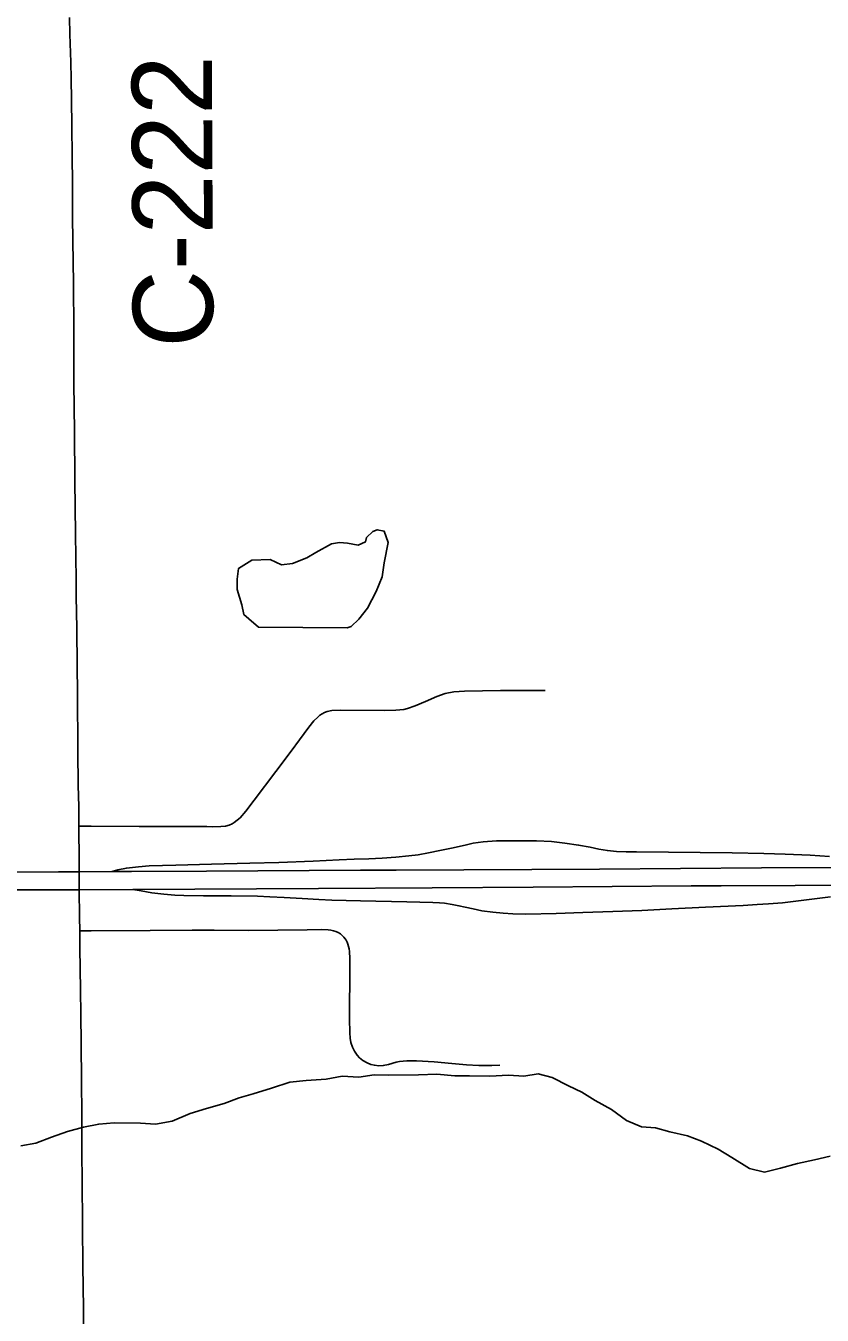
# Model space of a CAD drawing. Extents: x 0 to 34, y 0 to 22.
# Drawn here: x 19.216 to 19.78, y 18.221 to 19.134 of the extents above; entities that cross this region are included whole.
import ezdxf

# ---------------------------------------------------------------- set-up
doc = ezdxf.new("R2010")
doc.units = 0
for name, color, linetype in [('GM_X_County_Road', 7, 'Continuous'), ('GM_X_County_Road_Text', 7, 'Continuous'), ('GM_X_Interchange_Ramps', 7, 'Continuous'), ('GM_X_Interstate_Route', 7, 'Continuous'), ('GM_X_Minor_Lake', 7, 'Continuous'), ('GM_X_Minor_River', 7, 'Continuous'), ('GM_X_Township_Road', 7, 'Continuous')]:
    doc.layers.add(name, color=color, linetype=linetype)

msp = doc.modelspace()

# ---------------------------------------------------------------- linework, layer by layer
at = {"layer": 'GM_X_County_Road'}
for points in [[(19.25311, 18.56694), (19.25303, 18.58087), (19.25268, 18.59578), (19.25246, 18.62003), (19.25212, 18.66166), (19.25198, 18.68029), (19.25169, 18.70694), (19.25129, 18.72987), (19.25119, 18.74165), (19.25083, 18.77391), (19.25026, 18.81171), (19.25004, 18.84653), (19.24967, 18.88072), (19.24957, 18.90185), (19.24955, 18.91801), (19.24925, 18.95156), (19.24888, 18.9814), (19.24862, 18.9988), (19.24866, 19.02231), (19.24835, 19.04152), (19.24813, 19.06263), (19.24796, 19.08123), (19.24766, 19.09613), (19.24734, 19.10792), (19.24665, 19.1278), (19.24644, 19.13962)], [(19.25372, 18.49286), (19.25357, 18.50256), (19.25338, 18.52187), (19.25329, 18.53477), (19.25325, 18.54173), (19.25311, 18.56694)], [(19.257, 18.16696), (19.25674, 18.19016), (19.2563, 18.22556), (19.25602, 18.25597), (19.25569, 18.28392), (19.25549, 18.31685), (19.25531, 18.33487), (19.25521, 18.36284), (19.25499, 18.38645), (19.25467, 18.41317), (19.25441, 18.43367), (19.25425, 18.45105), (19.25391, 18.48083), (19.25372, 18.49286)]]:
    msp.add_lwpolyline(points, dxfattribs=at)
at = {"layer": 'GM_X_Interchange_Ramps'}
for points in [[(19.27664, 18.53491), (19.28082, 18.53605), (19.28679, 18.53735), (19.29537, 18.53828), (19.30301, 18.53886), (19.3217, 18.53936), (19.34715, 18.54004), (19.3743, 18.54077), (19.39487, 18.54129), (19.4192, 18.54235), (19.43746, 18.54314), (19.44801, 18.54357), (19.45856, 18.54401), (19.46787, 18.5444), (19.47755, 18.54502), (19.48679, 18.54599), (19.4935, 18.54683), (19.50078, 18.54822), (19.50876, 18.54976), (19.51715, 18.55157), (19.52681, 18.55367), (19.5324, 18.55493), (19.53954, 18.5559), (19.54905, 18.55659), (19.56304, 18.55658), (19.57731, 18.55672), (19.58793, 18.55621), (19.59732, 18.55503), (19.60712, 18.55363), (19.61537, 18.55209), (19.62152, 18.55082), (19.62754, 18.5497), (19.63383, 18.54913), (19.64083, 18.54885), (19.64822, 18.54877), (19.71595, 18.54826), (19.73831, 18.54777), (19.75332, 18.54725), (19.77119, 18.54639), (19.78481, 18.54563)], [(19.29138, 18.5221), (19.29721, 18.52114), (19.30479, 18.51989), (19.31321, 18.51885), (19.32111, 18.51825), (19.32744, 18.51801), (19.34137, 18.51776), (19.36089, 18.51779), (19.37959, 18.51736), (19.38831, 18.51703), (19.3986, 18.51651), (19.41138, 18.51585), (19.42321, 18.51511), (19.4322, 18.51465), (19.4527, 18.51408), (19.48544, 18.51356), (19.50393, 18.51303), (19.5085, 18.51272), (19.51204, 18.51241), (19.51744, 18.51157), (19.52232, 18.51074), (19.52678, 18.5097), (19.53249, 18.50845), (19.53863, 18.5072), (19.54631, 18.50615), (19.55371, 18.50534), (19.56044, 18.505), (19.56968, 18.50479), (19.59118, 18.50527), (19.6101, 18.50583), (19.63133, 18.50663), (19.65196, 18.50743), (19.67314, 18.50847), (19.69694, 18.50964), (19.72373, 18.51095), (19.73351, 18.51146), (19.74172, 18.51198), (19.75158, 18.5128), (19.7856, 18.51689)]]:
    msp.add_lwpolyline(points, dxfattribs=at)
at = {"layer": 'GM_X_Interstate_Route'}
for points in [[(18.06769, 18.52783), (18.1722, 18.52848), (18.31435, 18.52952), (18.34988, 18.52965), (18.42166, 18.52989), (18.446, 18.53), (18.50882, 18.53026), (18.56828, 18.53052), (18.64411, 18.5309), (18.69434, 18.53129), (18.74569, 18.53151), (18.75331, 18.53156), (18.80627, 18.53194), (18.85677, 18.5322), (18.89413, 18.53246), (18.91707, 18.53262), (18.95695, 18.5329), (19.02718, 18.53341), (19.07125, 18.53369), (19.14751, 18.53414), (19.1899, 18.5344), (19.23872, 18.53468), (19.25329, 18.53477), (19.27664, 18.53491)], [(19.27664, 18.53491), (19.29051, 18.53492), (19.34349, 18.53522), (19.45262, 18.53581), (19.47799, 18.53595), (19.622, 18.53662), (19.73655, 18.53749), (19.83709, 18.53803), (19.86787, 18.5382), (19.93261, 18.53855), (19.97923, 18.53851), (20.08241, 18.53907), (20.13865, 18.53937), (20.1689, 18.53957), (20.21364, 18.53988), (20.24381, 18.54008)], [(19.29138, 18.5221), (19.42279, 18.52291), (19.5034, 18.52345), (19.57482, 18.52392), (19.68676, 18.52473), (19.70803, 18.52489), (19.86531, 18.52561), (19.92565, 18.52583), (19.95161, 18.5259), (19.99078, 18.52624), (20.09682, 18.52682), (20.15767, 18.52716), (20.23203, 18.52749), (20.24381, 18.52755)], [(18.08051, 18.51603), (18.11562, 18.51622), (18.19066, 18.51693), (18.22011, 18.5172), (18.30805, 18.5173), (18.45088, 18.51818), (18.5161, 18.51859), (18.57828, 18.51881), (18.64181, 18.51904), (18.70848, 18.51922), (18.75336, 18.51946), (18.75612, 18.51947), (18.84606, 18.51994), (19.05087, 18.5216), (19.16279, 18.52205), (19.25254, 18.52186), (19.25338, 18.52187), (19.29138, 18.5221)]]:
    msp.add_lwpolyline(points, dxfattribs=at)
at = {"layer": 'GM_X_Minor_Lake'}
msp.add_line((19.38038, 18.70791), (19.44326, 18.70752), dxfattribs=at)
msp.add_lwpolyline([(19.44326, 18.70752), (19.44591, 18.70831), (19.45153, 18.71369), (19.4575, 18.72136), (19.46381, 18.73321), (19.46786, 18.74351), (19.46927, 18.7534), (19.47214, 18.76787), (19.4694, 18.77581), (19.46446, 18.77689), (19.46144, 18.77571), (19.45695, 18.77148), (19.45622, 18.76844), (19.45094, 18.76609), (19.44336, 18.76752), (19.43767, 18.76783), (19.432, 18.76701), (19.42108, 18.7608), (19.41469, 18.75693), (19.4045, 18.75301), (19.39656, 18.75216), (19.38857, 18.75586), (19.37569, 18.75533), (19.36629, 18.74952), (19.36524, 18.74191), (19.36532, 18.7347), (19.36847, 18.72372), (19.37006, 18.7169), (19.3735, 18.71391), (19.38038, 18.70791)], dxfattribs=at)
at = {"layer": 'GM_X_Minor_River'}
for points in [[(19.21212, 18.34057), (19.22271, 18.3426), (19.23364, 18.3469), (19.24496, 18.35084), (19.25629, 18.35401), (19.26725, 18.35604), (19.27822, 18.35693), (19.29679, 18.35677), (19.3074, 18.35614), (19.31912, 18.35818), (19.33193, 18.36365), (19.34364, 18.3672), (19.3561, 18.37077), (19.36666, 18.37469), (19.37647, 18.37747), (19.38969, 18.38142), (19.40252, 18.38575), (19.41424, 18.38703), (19.42825, 18.38795), (19.43959, 18.38999), (19.45134, 18.38937), (19.4623, 18.39101), (19.47215, 18.39075), (19.49374, 18.39101), (19.50661, 18.39154), (19.5195, 18.39017), (19.52973, 18.39029), (19.54412, 18.39008), (19.55737, 18.39062), (19.56836, 18.38999), (19.57857, 18.39163), (19.58845, 18.38909), (19.59988, 18.38314), (19.60939, 18.3787), (19.61893, 18.37274), (19.63036, 18.36641), (19.64105, 18.35857), (19.65171, 18.35413), (19.66156, 18.35349)], [(19.66156, 18.35349), (19.67182, 18.35057), (19.68435, 18.34768), (19.69424, 18.344), (19.70604, 18.33844), (19.71558, 18.33248), (19.72817, 18.32465), (19.7388, 18.32212), (19.75013, 18.32491), (19.76221, 18.32809), (19.7743, 18.33089), (19.78526, 18.3333)]]:
    msp.add_lwpolyline(points, dxfattribs=at)
at = {"layer": 'GM_X_Township_Road'}
for points in [[(19.25311, 18.56694), (19.26172, 18.56693), (19.29588, 18.56689), (19.32448, 18.56679), (19.34371, 18.56671), (19.34806, 18.56661), (19.3536, 18.56674), (19.35692, 18.56704), (19.35948, 18.56774), (19.36161, 18.5686), (19.36322, 18.56962), (19.36727, 18.573), (19.37134, 18.57755), (19.3774, 18.5854), (19.39275, 18.60573), (19.40353, 18.62016), (19.40944, 18.62815), (19.41606, 18.63722), (19.41963, 18.64165), (19.42238, 18.64433), (19.42385, 18.64555), (19.42536, 18.6466), (19.42706, 18.6476), (19.42905, 18.64831), (19.43222, 18.64883), (19.43854, 18.64922), (19.46966, 18.64887), (19.47766, 18.64922), (19.48339, 18.6497), (19.48581, 18.65026), (19.49132, 18.65221), (19.49867, 18.65538), (19.50667, 18.65891), (19.51263, 18.66094), (19.51884, 18.66219), (19.52636, 18.66271), (19.55186, 18.66314), (19.58343, 18.66299)], [(19.25372, 18.49286), (19.26189, 18.49293), (19.30356, 18.49327), (19.33341, 18.49334), (19.34896, 18.49333), (19.37321, 18.4932), (19.41489, 18.49371), (19.42493, 18.4938), (19.42972, 18.49358), (19.43169, 18.49328), (19.43349, 18.49292), (19.43523, 18.49238), (19.43684, 18.49166), (19.43834, 18.4907), (19.43966, 18.48968), (19.44085, 18.48843), (19.44175, 18.48729), (19.44246, 18.48627), (19.44319, 18.48495), (19.44372, 18.48339), (19.4442, 18.48184), (19.44461, 18.48016), (19.44486, 18.47819), (19.44507, 18.47336), (19.44507, 18.46767), (19.44493, 18.43053), (19.44499, 18.42066), (19.44522, 18.41688), (19.44582, 18.41387), (19.44703, 18.41048), (19.44834, 18.40777), (19.45032, 18.40478), (19.4519, 18.40303), (19.45415, 18.40112), (19.45722, 18.39936), (19.46001, 18.39834), (19.46248, 18.39769), (19.46564, 18.39738), (19.46872, 18.39753), (19.47235, 18.39822), (19.4779, 18.39991), (19.48033, 18.40035), (19.4854, 18.40087), (19.4923, 18.40078), (19.50479, 18.40014), (19.51721, 18.39903), (19.52771, 18.398), (19.53637, 18.39755), (19.54564, 18.39762), (19.55121, 18.39784)]]:
    msp.add_lwpolyline(points, dxfattribs=at)

# ---------------------------------------------------------------- texts
at = {"layer": 'GM_X_County_Road_Text'}
msp.add_text('C-222', height=0.056818, rotation=90.27389, dxfattribs=at).set_placement((19.34833, 18.90602))

doc.saveas('drawing.dxf')
